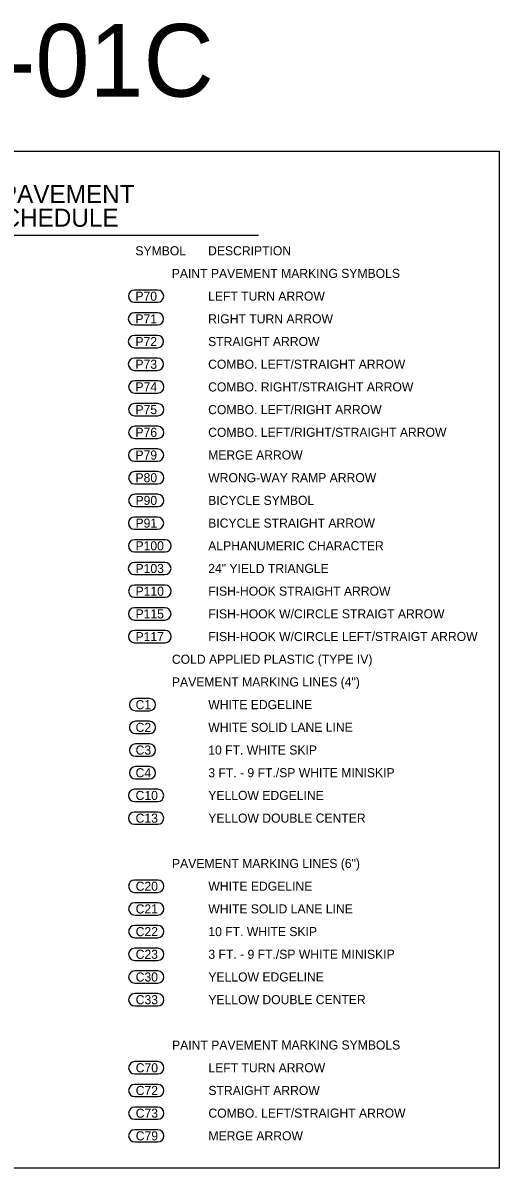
# Model space of a CAD drawing. Extents: x 2486454 to 2490507, y 369321 to 372999.
# Drawn here: x 2487627 to 2487994, y 369321 to 370204 of the extents above; entities that cross this region are included whole.
import ezdxf

# ---------------------------------------------------------------- set-up
doc = ezdxf.new("R2010")
doc.units = 0
for name, color, linetype in [('Default', 7, 'Continuous'), ('TC LABEL PM', 7, 'Continuous'), ('TC SHEET BORDER LINE THIN', 7, 'Continuous'), ('TC SHEET LAYOUT SHAPE', 7, 'Continuous'), ('TC SHEET TEXT', 7, 'Continuous')]:
    doc.layers.add(name, color=color, linetype=linetype)

msp = doc.modelspace()

# ---------------------------------------------------------------- linework, layer by layer
at = {"layer": 'TC LABEL PM'}
for p, q in [((2487731.06, 369997.89), (2487713.3, 369997.89)), ((2487730.96, 369980.39), (2487713.2, 369980.39)), ((2487713.3, 369988.46), (2487731.06, 369988.46)), ((2487713.2, 369970.96), (2487730.96, 369970.96)), ((2487730.96, 369962.89), (2487713.2, 369962.89)), ((2487713.2, 369953.46), (2487730.96, 369953.46)), ((2487730.94, 369945.39), (2487713.18, 369945.39)), ((2487713.18, 369935.96), (2487730.94, 369935.96)), ((2487731.12, 369927.89), (2487713.37, 369927.89)), ((2487713.37, 369918.46), (2487731.12, 369918.46)), ((2487731.13, 369910.39), (2487713.37, 369910.39)), ((2487713.37, 369900.96), (2487731.13, 369900.96)), ((2487731.14, 369892.89), (2487713.38, 369892.89)), ((2487713.38, 369883.46), (2487731.14, 369883.46)), ((2487731.03, 369875.39), (2487713.27, 369875.39)), ((2487713.27, 369865.96), (2487731.03, 369865.96)), ((2487731.12, 369857.89), (2487713.36, 369857.89)), ((2487713.36, 369848.46), (2487731.12, 369848.46)), ((2487731.13, 369840.39), (2487713.37, 369840.39)), ((2487713.37, 369830.96), (2487731.13, 369830.96)), ((2487731.03, 369822.89), (2487713.27, 369822.89)), ((2487713.27, 369813.46), (2487731.03, 369813.46)), ((2487736.78, 369805.39), (2487713.33, 369805.39)), ((2487713.33, 369795.96), (2487736.78, 369795.96)), ((2487736.65, 369787.89), (2487713.2, 369787.89)), ((2487713.2, 369778.46), (2487736.65, 369778.46)), ((2487736.8, 369770.39), (2487713.35, 369770.39)), ((2487713.35, 369760.96), (2487736.8, 369760.96)), ((2487736.67, 369752.89), (2487713.22, 369752.89)), ((2487713.22, 369743.46), (2487736.67, 369743.46)), ((2487736.75, 369735.39), (2487713.3, 369735.39)), ((2487713.3, 369725.96), (2487736.75, 369725.96)), ((2487724.73, 369682.89), (2487714.07, 369682.89)), ((2487714.07, 369673.46), (2487724.73, 369673.46)), ((2487724.74, 369665.39), (2487714.07, 369665.39)), ((2487714.07, 369655.96), (2487724.74, 369655.96)), ((2487724.75, 369647.89), (2487714.08, 369647.89)), ((2487714.08, 369638.46), (2487724.75, 369638.46)), ((2487724.76, 369630.39), (2487714.09, 369630.39)), ((2487714.09, 369620.96), (2487724.76, 369620.96)), ((2487731.08, 369612.89), (2487713.32, 369612.89)), ((2487713.32, 369603.46), (2487731.08, 369603.46)), ((2487731.09, 369595.39), (2487713.33, 369595.39)), ((2487713.33, 369585.96), (2487731.09, 369585.96)), ((2487731.11, 369542.89), (2487713.35, 369542.89)), ((2487713.35, 369533.46), (2487731.11, 369533.46)), ((2487731.12, 369525.39), (2487713.36, 369525.39)), ((2487713.36, 369515.96), (2487731.12, 369515.96)), ((2487731.12, 369507.89), (2487713.37, 369507.89)), ((2487713.37, 369498.46), (2487731.12, 369498.46)), ((2487731.13, 369490.39), (2487713.37, 369490.39)), ((2487713.37, 369480.96), (2487731.13, 369480.96)), ((2487731.14, 369472.89), (2487713.38, 369472.89)), ((2487713.38, 369463.46), (2487731.14, 369463.46)), ((2487731.15, 369455.39), (2487713.39, 369455.39)), ((2487713.39, 369445.96), (2487731.15, 369445.96)), ((2487731.12, 369402.89), (2487713.37, 369402.89)), ((2487713.37, 369393.46), (2487731.12, 369393.46)), ((2487731.13, 369385.39), (2487713.37, 369385.39)), ((2487713.37, 369375.96), (2487731.13, 369375.96)), ((2487731.14, 369367.89), (2487713.38, 369367.89)), ((2487713.38, 369358.46), (2487731.14, 369358.46)), ((2487731.15, 369350.39), (2487713.39, 369350.39)), ((2487713.39, 369340.96), (2487731.15, 369340.96))]:
    msp.add_line(p, q, dxfattribs=at)
for centre, start, end in [((2487713.3, 369993.17), 90, 270), ((2487731.06, 369993.17), 270, 90), ((2487713.2, 369975.67), 90, 270), ((2487730.96, 369975.67), 270, 90), ((2487713.2, 369958.17), 90, 270), ((2487730.96, 369958.17), 270, 90), ((2487713.18, 369940.67), 90, 270), ((2487730.94, 369940.67), 270, 90), ((2487713.37, 369923.17), 90, 270), ((2487731.12, 369923.17), 270, 90), ((2487713.37, 369905.67), 90, 270), ((2487731.13, 369905.67), 270, 90), ((2487713.38, 369888.17), 90, 270), ((2487731.14, 369888.17), 270, 90), ((2487713.27, 369870.67), 90, 270), ((2487731.03, 369870.67), 270, 90), ((2487713.36, 369853.17), 90, 270), ((2487731.12, 369853.17), 270, 90), ((2487713.37, 369835.67), 90, 270), ((2487731.13, 369835.67), 270, 90), ((2487713.27, 369818.17), 90, 270), ((2487731.03, 369818.17), 270, 90), ((2487713.33, 369800.68), 90, 270), ((2487736.78, 369800.68), 270, 90), ((2487713.2, 369783.18), 90, 270), ((2487736.65, 369783.18), 270, 90), ((2487713.35, 369765.68), 90, 270), ((2487736.8, 369765.68), 270, 90), ((2487713.22, 369748.18), 90, 270), ((2487736.67, 369748.18), 270, 90), ((2487713.3, 369730.68), 90, 270), ((2487736.75, 369730.68), 270, 90), ((2487714.07, 369678.17), 90, 270), ((2487724.73, 369678.17), 270, 90), ((2487714.07, 369660.67), 90, 270), ((2487724.74, 369660.67), 270, 90), ((2487714.08, 369643.17), 90, 270), ((2487724.75, 369643.17), 270, 90), ((2487714.09, 369625.67), 90, 270), ((2487724.76, 369625.67), 270, 90), ((2487713.32, 369608.17), 90, 270), ((2487731.08, 369608.17), 270, 90), ((2487713.33, 369590.67), 90, 270), ((2487731.09, 369590.67), 270, 90), ((2487713.35, 369538.17), 90, 270), ((2487731.11, 369538.17), 270, 90), ((2487713.36, 369520.67), 90, 270), ((2487731.12, 369520.67), 270, 90), ((2487713.37, 369503.17), 90, 270), ((2487731.12, 369503.17), 270, 90), ((2487713.37, 369485.67), 90, 270), ((2487731.13, 369485.67), 270, 90), ((2487713.38, 369468.17), 90, 270), ((2487731.14, 369468.17), 270, 90), ((2487713.39, 369450.67), 90, 270), ((2487731.15, 369450.67), 270, 90), ((2487713.37, 369398.17), 90, 270), ((2487731.12, 369398.17), 270, 90), ((2487713.37, 369380.67), 90, 270), ((2487731.13, 369380.67), 270, 90), ((2487713.38, 369363.17), 90, 270), ((2487731.14, 369363.17), 270, 90), ((2487713.39, 369345.67), 90, 270), ((2487731.15, 369345.67), 270, 90)]:
    msp.add_arc(centre, 4.72, start, end, dxfattribs=at)
at = {"layer": 'TC SHEET BORDER LINE THIN'}
msp.add_line((2487488.27, 370040.3), (2487808.8, 370040.3), dxfattribs=at)
at = {"layer": 'TC SHEET LAYOUT SHAPE'}
msp.add_lwpolyline([(2487348.46, 370095.07), (2487358.46, 370105.07), (2487994.1, 370105.07), (2487994.1, 369320.81), (2487348.46, 369320.81)], close=True, dxfattribs=at)

# ---------------------------------------------------------------- texts
at = {"layer": 'Default'}
for s, p in [('SYMBOL', (2487713.92, 370024.67)), ('DESCRIPTION', (2487769.92, 370024.69)), ('PAINT PAVEMENT MARKING SYMBOLS', (2487741.93, 370007.18)), ('P70', (2487713.94, 369989.67)), ('LEFT TURN ARROW', (2487769.94, 369989.69)), ('P71', (2487713.95, 369972.17)), ('RIGHT TURN ARROW', (2487769.95, 369972.19)), ('P72', (2487713.95, 369954.67)), ('STRAIGHT ARROW', (2487769.95, 369954.69)), ('COMBO. LEFT/STRAIGHT ARROW', (2487769.96, 369937.19)), ('P73', (2487713.96, 369937.17)), ('COMBO. RIGHT/STRAIGHT ARROW', (2487769.97, 369919.69)), ('P74', (2487713.97, 369919.67)), ('P75', (2487713.98, 369902.17)), ('COMBO. LEFT/RIGHT ARROW', (2487769.98, 369902.19)), ('P76', (2487713.98, 369884.67)), ('COMBO. LEFT/RIGHT/STRAIGHT ARROW', (2487769.98, 369884.69)), ('P79', (2487713.99, 369867.17)), ('MERGE ARROW', (2487769.99, 369867.19)), ('P80', (2487714, 369849.67)), ('WRONG-WAY RAMP ARROW', (2487770, 369849.69)), ('P90', (2487714.01, 369832.17)), ('BICYCLE SYMBOL', (2487770.01, 369832.19)), ('P91', (2487714.01, 369814.67)), ('BICYCLE STRAIGHT ARROW', (2487770.01, 369814.69)), ('P100', (2487714.02, 369797.17)), ('ALPHANUMERIC CHARACTER', (2487770.02, 369797.19)), ('P103', (2487714.03, 369779.67)), ('24" YIELD TRIANGLE', (2487770.03, 369779.69)), ('P110', (2487714.04, 369762.17)), ('FISH-HOOK STRAIGHT ARROW', (2487770.04, 369762.19)), ('P115', (2487714.04, 369744.67)), ('FISH-HOOK W/CIRCLE STRAIGT ARROW', (2487770.04, 369744.69)), ('P117', (2487714.05, 369727.17)), ('FISH-HOOK W/CIRCLE LEFT/STRAIGT ARROW', (2487770.05, 369727.19)), ('COLD APPLIED PLASTIC (TYPE IV)', (2487742.04, 369709.68)), ('PAVEMENT MARKING LINES (4")', (2487742.05, 369692.18)), ('C1', (2487714.06, 369674.67)), ('WHITE EDGELINE', (2487770.06, 369674.69)), ('C2', (2487714.07, 369657.17)), ('WHITE SOLID LANE LINE', (2487770.07, 369657.19)), ('C3', (2487714.07, 369639.67)), ('10 FT. WHITE SKIP', (2487770.07, 369639.69)), ('C4', (2487714.08, 369622.17)), ('3 FT. - 9 FT./SP WHITE MINISKIP', (2487770.08, 369622.19)), ('C10', (2487714.09, 369604.67)), ('YELLOW EDGELINE', (2487770.09, 369604.69)), ('C13', (2487714.09, 369587.17)), ('YELLOW DOUBLE CENTER', (2487770.09, 369587.19)), ('PAVEMENT MARKING LINES (6")', (2487742.11, 369552.18)), ('C20', (2487714.12, 369534.67)), ('WHITE EDGELINE', (2487770.12, 369534.69)), ('C21', (2487714.12, 369517.17)), ('WHITE SOLID LANE LINE', (2487770.12, 369517.19)), ('C22', (2487714.13, 369499.67)), ('10 FT. WHITE SKIP', (2487770.13, 369499.69)), ('C23', (2487714.14, 369482.17)), ('3 FT. - 9 FT./SP WHITE MINISKIP', (2487770.14, 369482.19)), ('C30', (2487714.15, 369464.67)), ('YELLOW EDGELINE', (2487770.15, 369464.69)), ('C33', (2487714.15, 369447.17)), ('YELLOW DOUBLE CENTER', (2487770.15, 369447.19)), ('PAINT PAVEMENT MARKING SYMBOLS', (2487742.17, 369412.18)), ('C70', (2487714.18, 369394.67)), ('LEFT TURN ARROW', (2487770.18, 369394.69)), ('C72', (2487714.18, 369377.17)), ('STRAIGHT ARROW', (2487770.18, 369377.19)), ('C73', (2487714.19, 369359.67)), ('COMBO. LEFT/STRAIGHT ARROW', (2487770.19, 369359.69)), ('C79', (2487714.2, 369342.17)), ('MERGE ARROW', (2487770.2, 369342.19))]:
    msp.add_text(s, height=7, rotation=0.02426, dxfattribs=at).set_placement(p)
at = {"layer": 'TC SHEET LAYOUT SHAPE'}
msp.add_text('TCP-01C', height=55.996, rotation=0.00008, dxfattribs=at).set_placement((2487462.21, 370147.07))
at = {"layer": 'TC SHEET TEXT'}
for s, p in [('TEMPORARY PAVEMENT', (2487486.52, 370065.03)), ('MARKING SCHEDULE', (2487506.46, 370046.67))]:
    msp.add_text(s, height=13.9991, rotation=0.00008, dxfattribs=at).set_placement(p)

doc.saveas('drawing.dxf')
